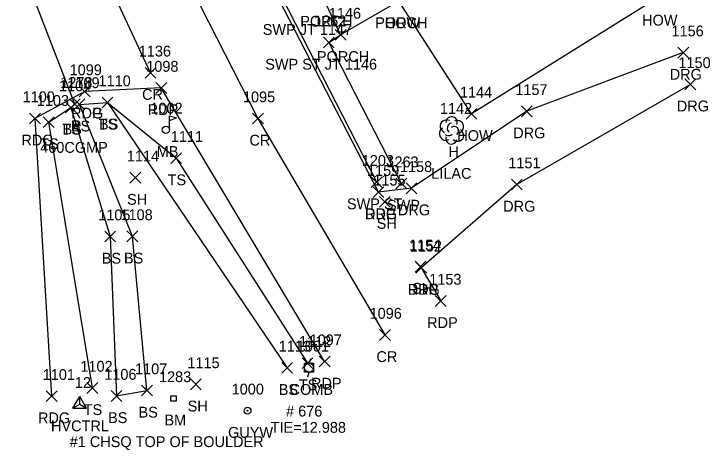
# Model space of a CAD drawing. Extents: x 462930 to 463548, y 29607 to 30453.
# Drawn here: x 463353.81 to 463393, y 29941.87 to 29966.42 of the extents above; entities that cross this region are included whole.
import ezdxf

# ---------------------------------------------------------------- set-up
doc = ezdxf.new("R2010")
doc.units = 0
for name, color, linetype in [('C_A', 7, 'Continuous'), ('C_C', 7, 'Continuous'), ('C_I', 7, 'Continuous'), ('CPBM', 7, 'Continuous'), ('CPSM', 7, 'Continuous'), ('D_A', 7, 'Continuous'), ('D_C', 7, 'Continuous'), ('D_I', 7, 'Continuous'), ('D_TIC', 7, 'Continuous'), ('DCP', 7, 'Continuous'), ('L_A', 7, 'Continuous'), ('L_C', 7, 'Continuous'), ('L_I', 7, 'Continuous'), ('L_TIC', 7, 'Continuous'), ('LBC', 7, 'Continuous'), ('LBF', 7, 'Continuous'), ('LELB', 7, 'Continuous'), ('LMB', 7, 'Continuous'), ('LTD', 7, 'Continuous'), ('P_A', 7, 'Continuous'), ('P_I', 7, 'Continuous'), ('P_TIC', 7, 'Continuous'), ('PET', 7, 'Continuous'), ('PEU', 7, 'Continuous'), ('PRC', 7, 'Continuous'), ('R_A', 7, 'Continuous'), ('R_I', 7, 'Continuous'), ('R_TIC', 7, 'Continuous'), ('RDG', 7, 'Continuous'), ('RSW', 7, 'Continuous'), ('U_A', 7, 'Continuous'), ('U_C', 7, 'Continuous'), ('U_I', 7, 'Continuous'), ('UP', 7, 'Continuous'), ('UPGW', 7, 'Continuous')]:
    doc.layers.add(name, color=color, linetype=linetype)

msp = doc.modelspace()

# ---------------------------------------------------------------- linework, layer by layer
at = {"layer": 'CPBM'}
for p, q in [((463362.645, 29944.627), (463362.645, 29944.932)), ((463362.645, 29944.932), (463362.95, 29944.932)), ((463362.798, 29944.78), (463362.798, 29944.78)), ((463362.798, 29944.78), (463362.798, 29944.78)), ((463362.95, 29944.932), (463362.95, 29944.627)), ((463362.95, 29944.627), (463362.645, 29944.627))]:
    msp.add_line(p, q, dxfattribs=at)
at = {"layer": 'CPSM'}
for p, q in [((463357.133, 29944.233), (463357.514, 29944.893)), ((463357.895, 29944.233), (463357.514, 29944.893)), ((463357.514, 29944.453), (463357.514, 29944.893)), ((463357.133, 29944.233), (463357.514, 29944.453)), ((463357.514, 29944.453), (463357.514, 29944.453)), ((463357.514, 29944.453), (463357.895, 29944.233)), ((463357.133, 29944.233), (463357.895, 29944.233))]:
    msp.add_line(p, q, dxfattribs=at)
at = {"layer": 'D_TIC'}
for points in [[(463356.937, 29961.042), (463357.547, 29961.652)], [(463357.547, 29961.042), (463356.937, 29961.652)]]:
    msp.add_lwpolyline(points, dxfattribs=at)
at = {"layer": 'DCP'}
msp.add_lwpolyline([(463357.242, 29961.347), (463347.606, 29986.199)], dxfattribs=at)
at = {"layer": 'L_TIC'}
for points in [[(463371.898, 29964.937), (463372.508, 29965.547)], [(463372.508, 29964.937), (463371.898, 29965.547)], [(463357.189, 29961.027), (463357.799, 29961.637)], [(463357.799, 29961.027), (463357.189, 29961.637)], [(463358.769, 29961.135), (463359.379, 29961.745)], [(463359.379, 29961.135), (463358.769, 29961.745)], [(463358.769, 29961.135), (463359.379, 29961.745)], [(463359.379, 29961.135), (463358.769, 29961.745)], [(463356.717, 29960.851), (463357.327, 29961.461)], [(463357.327, 29960.851), (463356.717, 29961.461)], [(463356.717, 29960.851), (463357.327, 29961.461)], [(463357.327, 29960.851), (463356.717, 29961.461)], [(463379.261, 29960.49), (463379.871, 29961.1)], [(463379.871, 29960.49), (463379.261, 29961.1)], [(463355.465, 29960.026), (463356.075, 29960.636)], [(463356.075, 29960.026), (463355.465, 29960.636)], [(463362.642, 29957.997), (463363.252, 29958.607)], [(463363.252, 29957.997), (463362.642, 29958.607)], [(463360.337, 29956.899), (463360.947, 29957.509)], [(463360.947, 29956.899), (463360.337, 29957.509)], [(463374.386, 29955.544), (463374.996, 29956.154)], [(463374.996, 29955.544), (463374.386, 29956.154)], [(463358.925, 29953.584), (463359.535, 29954.194)], [(463359.535, 29953.584), (463358.925, 29954.194)], [(463360.176, 29953.594), (463360.786, 29954.204)], [(463360.786, 29953.594), (463360.176, 29954.204)], [(463376.39, 29951.891), (463377, 29952.501)], [(463377, 29951.891), (463376.39, 29952.501)], [(463368.887, 29946.194), (463369.497, 29946.804)], [(463369.497, 29946.194), (463368.887, 29946.804)], [(463370.029, 29946.456), (463370.639, 29947.066)], [(463370.639, 29946.456), (463370.029, 29947.066)], [(463357.92, 29945.06), (463358.53, 29945.67)], [(463358.53, 29945.06), (463357.92, 29945.67)], [(463363.746, 29945.261), (463364.356, 29945.871)], [(463364.356, 29945.261), (463363.746, 29945.871)], [(463359.281, 29944.609), (463359.891, 29945.219)], [(463359.891, 29944.609), (463359.281, 29945.219)], [(463360.996, 29944.917), (463361.606, 29945.527)], [(463361.606, 29944.917), (463360.996, 29945.527)]]:
    msp.add_lwpolyline(points, dxfattribs=at)
at = {"layer": 'LBC'}
msp.add_lwpolyline([(463389.972, 29967.29), (463379.566, 29960.795), (463375.486, 29967.144)], dxfattribs=at)
at = {"layer": 'LBF'}
msp.add_lwpolyline([(463375.486, 29967.144), (463372.203, 29965.242), (463371.266, 29967.227), (463374.355, 29969.012), (463372.963, 29971.338)], dxfattribs=at)
at = {"layer": 'LELB'}
for points in [[(463357.022, 29961.156), (463359.23, 29953.889), (463359.586, 29944.914), (463361.301, 29945.222), (463360.481, 29953.899), (463357.494, 29961.332), (463359.074, 29961.44), (463369.192, 29946.499)], [(463359.074, 29961.44), (463362.947, 29958.302), (463370.334, 29946.761)], [(463358.225, 29945.365), (463355.77, 29960.331), (463357.022, 29961.156)]]:
    msp.add_lwpolyline(points, dxfattribs=at)
at = {"layer": 'LMB'}
for p, q in [((463362.562, 29960.691), (463362.956, 29960.574)), ((463362.564, 29959.901), (463362.564, 29960.691)), ((463362.564, 29960.417), (463362.955, 29960.572)), ((463362.364, 29959.898), (463362.364, 29959.898))]:
    msp.add_line(p, q, dxfattribs=at)
msp.add_circle((463362.364, 29959.898), 0.2, dxfattribs=at)
at = {"layer": 'LTD'}
msp.add_line((463378.438, 29959.884), (463378.438, 29959.884), dxfattribs=at)
msp.add_line((463378.438, 29959.884), (463378.438, 29959.884), dxfattribs=at)
msp.add_arc((463378.452, 29960.321), 0.319, 335.5272, 180.9563, dxfattribs=at)
for centre, major_axis, ratio, start_param, end_param in [((463378.197, 29960.087), (0.369, -0.156), 0.895232, 1.570796, 4.712389), ((463378.755, 29960.062), (-0.348, -0.147), 0.949671, 1.570796, 4.712389), ((463378.374, 29960.024), (-0.063, -0.241), 0.645439, 3.141593, 6.283185), ((463378.59, 29959.833), (-0.152, 0.203), 0.989748, 3.141593, 6.283185), ((463378.108, 29959.668), (0.178, -0.317), 0.959034, 3.141593, 6.283185), ((463378.298, 29959.655), (-0.19, -0.025), 0.423636, 0, 3.141593), ((463378.743, 29959.63), (-0.332, 0.241), 0.841452, 1.570796, 4.712389), ((463378.438, 29959.427), (0.081, 0.323), 0.942809, 1.570796, 4.712389)]:
    msp.add_ellipse(centre, major_axis=major_axis, ratio=ratio, start_param=start_param, end_param=end_param, dxfattribs=at)
at = {"layer": 'P_TIC'}
for points in [[(463361.198, 29962.806), (463361.808, 29963.416)], [(463361.808, 29962.806), (463361.198, 29963.416)], [(463361.8, 29961.948), (463362.41, 29962.558)], [(463362.41, 29961.948), (463361.8, 29962.558)], [(463357.489, 29961.755), (463358.099, 29962.365)], [(463358.099, 29961.755), (463357.489, 29962.365)], [(463357.489, 29961.755), (463358.099, 29962.365)], [(463358.099, 29961.755), (463357.489, 29962.365)], [(463354.691, 29960.235), (463355.301, 29960.845)], [(463355.301, 29960.235), (463354.691, 29960.845)], [(463367.243, 29960.229), (463367.853, 29960.839)], [(463367.853, 29960.229), (463367.243, 29960.839)], [(463374.033, 29956.086), (463374.643, 29956.696)], [(463374.643, 29956.086), (463374.033, 29956.696)], [(463376.437, 29951.829), (463377.047, 29952.439)], [(463377.047, 29951.829), (463376.437, 29952.439)], [(463377.533, 29949.961), (463378.143, 29950.571)], [(463378.143, 29949.961), (463377.533, 29950.571)], [(463374.39, 29948.044), (463375, 29948.654)], [(463375, 29948.044), (463374.39, 29948.654)], [(463370.995, 29946.55), (463371.605, 29947.16)], [(463371.605, 29946.55), (463370.995, 29947.16)], [(463355.626, 29944.597), (463356.236, 29945.207)], [(463356.236, 29944.597), (463355.626, 29945.207)]]:
    msp.add_lwpolyline(points, dxfattribs=at)
at = {"layer": 'PET'}
for points in [[(463374.338, 29956.391), (463367.555, 29969.533), (463365.556, 29974.625), (463364.583, 29976.896), (463356.695, 29995.475), (463352.505, 30009.098), (463350.167, 30017.966), (463347.98, 30027.115), (463347.733, 30028.32), (463346.051, 30037.294), (463343.907, 30048.483), (463342.761, 30054.643), (463342.551, 30055.85), (463341.301, 30062.483), (463338.432, 30077.399), (463338.227, 30078.623), (463337.48, 30086.968), (463337.479, 30088.196), (463338.474, 30099.226), (463339.751, 30104.374), (463341.961, 30110.783)], [(463371.3, 29946.855), (463362.105, 29962.253), (463357.794, 29962.06)], [(463376.742, 29952.134), (463377.838, 29950.266)]]:
    msp.add_lwpolyline(points, dxfattribs=at)
at = {"layer": 'PEU'}
msp.add_lwpolyline([(463357.794, 29962.06), (463354.996, 29960.54), (463355.931, 29944.902)], dxfattribs=at)
at = {"layer": 'PRC'}
for points in [[(463337.978, 30112.385), (463335.087, 30099.771), (463333.576, 30084.385), (463334.686, 30068.796), (463337.03, 30053.748), (463339.908, 30038.01), (463343.632, 30023.045), (463346.617, 30012.904), (463351.044, 29997.524), (463354.76, 29987.177), (463360.584, 29974.202), (463367.548, 29960.534), (463374.695, 29948.349)], [(463361.503, 29963.111), (463356.689, 29973.422), (463352.514, 29982.851), (463349.93, 29989.203)]]:
    msp.add_lwpolyline(points, dxfattribs=at)
at = {"layer": 'R_TIC'}
for points in [[(463371.235, 29964.505), (463371.845, 29965.115)], [(463371.845, 29964.505), (463371.235, 29965.115)], [(463391.188, 29963.94), (463391.798, 29964.55)], [(463391.798, 29963.94), (463391.188, 29964.55)], [(463391.587, 29962.154), (463392.197, 29962.764)], [(463392.197, 29962.154), (463391.587, 29962.764)], [(463382.378, 29960.638), (463382.988, 29961.248)], [(463382.988, 29960.638), (463382.378, 29961.248)], [(463373.93, 29956.647), (463374.54, 29957.257)], [(463374.54, 29956.647), (463373.93, 29957.257)], [(463375.311, 29956.567), (463375.921, 29957.177)], [(463375.921, 29956.567), (463375.311, 29957.177)], [(463381.813, 29956.511), (463382.423, 29957.121)], [(463382.423, 29956.511), (463381.813, 29957.121)], [(463374.033, 29956.086), (463374.643, 29956.696)], [(463374.643, 29956.086), (463374.033, 29956.696)], [(463375.885, 29956.304), (463376.495, 29956.914)], [(463376.495, 29956.304), (463375.885, 29956.914)], [(463376.437, 29951.829), (463377.047, 29952.439)], [(463377.047, 29951.829), (463376.437, 29952.439)]]:
    msp.add_lwpolyline(points, dxfattribs=at)
at = {"layer": 'RDG'}
for points in [[(463391.493, 29964.245), (463382.683, 29960.943), (463376.19, 29956.609), (463374.338, 29956.391)], [(463391.892, 29962.459), (463382.118, 29956.816), (463376.742, 29952.134)]]:
    msp.add_lwpolyline(points, dxfattribs=at)
at = {"layer": 'RSW'}
for points in [[(463374.235, 29956.952), (463367.745, 29969.631), (463365.689, 29974.684), (463364.801, 29976.975), (463360.584, 29986.798), (463357.266, 29995.548), (463352.711, 30009.142), (463350.357, 30017.977), (463347.93, 30028.371), (463346.21, 30037.33), (463344.933, 30043.874), (463342.934, 30054.68), (463342.697, 30055.906), (463341.529, 30062.506)], [(463371.54, 29964.81), (463372.203, 29965.242)], [(463371.54, 29964.81), (463375.616, 29956.872)]]:
    msp.add_lwpolyline(points, dxfattribs=at)
at = {"layer": 'UP'}
for p, q in [((463370.176, 29946.247), (463370.176, 29946.755)), ((463370.176, 29946.755), (463370.684, 29946.755)), ((463370.506, 29947.009), (463370.43, 29946.755)), ((463370.684, 29946.755), (463370.684, 29946.247)), ((463370.43, 29946.501), (463370.43, 29946.501)), ((463370.684, 29946.247), (463370.176, 29946.247)), ((463370.354, 29945.993), (463370.43, 29946.247))]:
    msp.add_line(p, q, dxfattribs=at)
msp.add_circle((463370.43, 29946.501), 0.254, dxfattribs=at)
at = {"layer": 'UPGW'}
for radius in [0.191, 0.0254]:
    msp.add_circle((463366.963, 29944.085), radius, dxfattribs=at)

# ---------------------------------------------------------------- texts
at = {"layer": 'C_A'}
for s, p in [('BM', (463362.284, 29943.256)), ('HVCTRL', (463355.896, 29942.929))]:
    msp.add_text(s, height=0.6096, dxfattribs=at).set_placement(p)
at = {"layer": 'C_C'}
msp.add_text('#1 CHSQ TOP OF BOULDER', height=0.6096, dxfattribs=at).set_placement((463356.949, 29942.037))
at = {"layer": 'C_I'}
for s, p in [('12', (463357.24, 29945.367)), ('1283', (463361.977, 29945.694))]:
    msp.add_text(s, height=0.6096, dxfattribs=at).set_placement(p)
at = {"layer": 'D_A'}
msp.add_text('P', height=0.61, dxfattribs=at).set_placement((463357.052, 29959.823))
at = {"layer": 'D_C'}
msp.add_text('460CGMP', height=0.6096, dxfattribs=at).set_placement((463355.291, 29958.604))
at = {"layer": 'D_I'}
msp.add_text('1278', height=0.6096, dxfattribs=at).set_placement((463356.421, 29962.261))
at = {"layer": 'L_A'}
for s, height, p in [('HOW', 0.6096, (463389.175, 29965.766)), ('PORCH', 0.6096, (463369.932, 29965.703)), ('PORCH', 0.6096, (463374.152, 29965.62)), ('HOW', 0.6096, (463374.689, 29965.62)), ('PORCH', 0.6096, (463370.869, 29963.718)), ('TS', 0.6096, (463358.589, 29959.916)), ('BS', 0.6096, (463358.599, 29959.916)), ('TS', 0.6096, (463356.537, 29959.632)), ('BS', 0.6096, (463356.547, 29959.632)), ('BS', 0.6096, (463357.019, 29959.808)), ('HOW', 0.6096, (463378.769, 29959.271)), ('TS', 0.6096, (463355.285, 29958.807)), ('MB', 0.6096, (463361.848, 29958.374)), ('H', 0.61, (463378.265, 29958.36)), ('TS', 0.6096, (463362.462, 29956.778)), ('SH', 0.6096, (463360.181, 29955.68)), ('SH', 0.6096, (463374.23, 29954.325)), ('BS', 0.6096, (463358.755, 29952.365)), ('BS', 0.6096, (463360.006, 29952.375)), ('SH', 0.6096, (463376.234, 29950.672)), ('BS', 0.6096, (463368.717, 29944.975)), ('TS', 0.6096, (463369.849, 29945.237)), ('TS', 0.6096, (463357.74, 29943.841)), ('SH', 0.6096, (463363.59, 29944.042)), ('BS', 0.6096, (463359.111, 29943.39)), ('BS', 0.6096, (463360.826, 29943.698))]:
    msp.add_text(s, height=height, dxfattribs=at).set_placement(p)
at = {"layer": 'L_C'}
msp.add_text('LILAC', height=0.6096, dxfattribs=at).set_placement((463377.303, 29957.141))
at = {"layer": 'L_I'}
for s, p in [('1146', (463371.538, 29966.156)), ('1109', (463356.82, 29962.246)), ('1110', (463358.573, 29962.354)), ('1110', (463358.573, 29962.354)), ('1104', (463356.35, 29962.07)), ('1104', (463356.35, 29962.07)), ('1144', (463378.918, 29961.709)), ('1103', (463355.098, 29961.245)), ('1002', (463361.495, 29960.812)), ('1142', (463377.79, 29960.798)), ('1111', (463362.645, 29959.216)), ('1114', (463360.167, 29958.118)), ('1155', (463374.043, 29956.763)), ('1105', (463358.558, 29954.803)), ('1108', (463359.809, 29954.813)), ('1154', (463376.047, 29953.11)), ('1113', (463368.717, 29947.413)), ('1112', (463369.859, 29947.675)), ('1102', (463357.553, 29946.279)), ('1107', (463360.629, 29946.136)), ('1115', (463363.576, 29946.48)), ('1106', (463358.897, 29945.828))]:
    msp.add_text(s, height=0.6096, dxfattribs=at).set_placement(p)
at = {"layer": 'P_A'}
for s, p in [('CR', (463361.025, 29961.587)), ('RDP', (463361.339, 29960.729)), ('RDG', (463357.028, 29960.536)), ('RDP', (463357.028, 29960.536)), ('RDG', (463354.23, 29959.016)), ('CR', (463367.07, 29959.01)), ('RDP', (463373.572, 29954.867)), ('RDP', (463375.976, 29950.61)), ('RDP', (463377.072, 29948.742)), ('CR', (463374.217, 29946.825)), ('RDP', (463370.534, 29945.331)), ('RDG', (463355.165, 29943.378))]:
    msp.add_text(s, height=0.6096, dxfattribs=at).set_placement(p)
at = {"layer": 'P_I'}
for s, p in [('1136', (463360.838, 29964.025)), ('1099', (463356.947, 29962.974)), ('1099', (463356.947, 29962.974)), ('1098', (463361.26, 29963.167)), ('1100', (463354.298, 29961.454)), ('1095', (463366.703, 29961.448)), ('1159', (463373.688, 29957.305)), ('1152', (463376.094, 29953.048)), ('1153', (463377.19, 29951.18)), ('1096', (463373.833, 29949.263)), ('1097', (463370.455, 29947.769)), ('1101', (463355.432, 29945.816))]:
    msp.add_text(s, height=0.6096, dxfattribs=at).set_placement(p)
at = {"layer": 'R_A'}
for s, p in [('SWP JT 1147', (463367.816, 29965.242)), ('SWP ST JT 1146', (463367.957, 29963.286)), ('DRG', (463390.727, 29962.721)), ('DRG', (463391.126, 29960.935)), ('DRG', (463381.917, 29959.419)), ('SWP ST', (463372.557, 29955.428)), ('SWP', (463374.812, 29955.348)), ('DRG', (463381.352, 29955.292)), ('DRG', (463373.572, 29954.867)), ('DRG', (463375.424, 29955.085)), ('DRG', (463375.976, 29950.61))]:
    msp.add_text(s, height=0.6096, dxfattribs=at).set_placement(p)
at = {"layer": 'R_I'}
for s, p in [('1262', (463370.705, 29965.724)), ('1156', (463390.828, 29965.159)), ('1150', (463391.218, 29963.373)), ('1157', (463382.035, 29961.857)), ('1203', (463373.39, 29957.866)), ('1263', (463374.781, 29957.786)), ('1158', (463375.542, 29957.523)), ('1151', (463381.643, 29957.73)), ('1159', (463373.688, 29957.305)), ('1152', (463376.094, 29953.048))]:
    msp.add_text(s, height=0.6096, dxfattribs=at).set_placement(p)
at = {"layer": 'U_A'}
for s, p in [('COMB', (463369.328, 29944.977)), ('GUYW', (463365.864, 29942.561))]:
    msp.add_text(s, height=0.6096, dxfattribs=at).set_placement(p)
at = {"layer": 'U_C'}
for s, p in [('# 676', (463369.132, 29943.758)), ('TIE=12.988', (463368.265, 29942.843))]:
    msp.add_text(s, height=0.6096, dxfattribs=at).set_placement(p)
at = {"layer": 'U_I'}
for s, p in [('1001', (463369.734, 29947.415)), ('1000', (463366.068, 29944.999))]:
    msp.add_text(s, height=0.6096, dxfattribs=at).set_placement(p)

doc.saveas('drawing.dxf')
